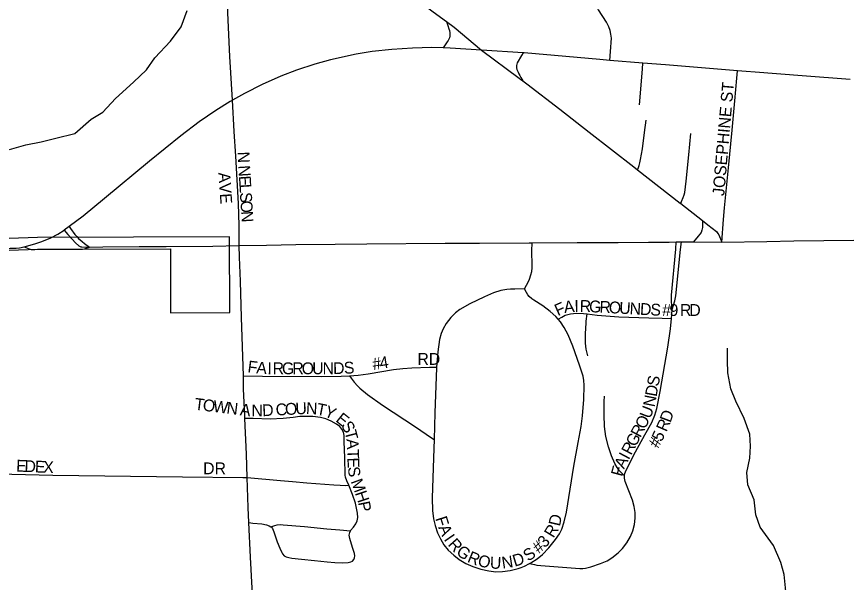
# Model space of a CAD drawing. Extents: x 1442749 to 1756758, y 235267 to 677782.
# Drawn here: x 1585804 to 1589318, y 527823 to 530215 of the extents above; entities that cross this region are included whole.
import ezdxf

# ---------------------------------------------------------------- set-up
doc = ezdxf.new("R2010")
doc.units = 0
for name, color, linetype in [('GM_X_City_Street', 7, 'Continuous'), ('GM_X_City_Street_Text', 7, 'Continuous'), ('GM_X_Corporation', 7, 'Continuous'), ('GM_X_Interchange_Ramps', 7, 'Continuous'), ('GM_X_Minor_River', 7, 'Continuous'), ('GM_X_State_Route', 7, 'Continuous'), ('GM_X_US_Route', 7, 'Continuous')]:
    doc.layers.add(name, color=color, linetype=linetype)

msp = doc.modelspace()

# ---------------------------------------------------------------- linework, layer by layer
at = {"layer": 'GM_X_City_Street'}
for points in [[(1586717, 529861.9), (1586706.7, 530046.1), (1586695.3, 530294.8), (1586687.2, 530448.6), (1586673.8, 530772)], [(1588313.2, 530030.2), (1588316.3, 530068.1), (1588319.9, 530123.8), (1588318.2, 530141.2), (1588315.2, 530155.9), (1588309.4, 530172.5), (1588299.5, 530192.3), (1588265.4, 530244.4), (1588253.4, 530268.3), (1588241.9, 530299.6), (1588241.1, 530303)], [(1588438.4, 529841.4), (1588443.2, 529890.8), (1588451.7, 529994.9), (1588453.6, 530018.8)], [(1588787.1, 529262), (1588794.1, 529357.4), (1588797.9, 529406.1), (1588814.7, 529575.5), (1588830.2, 529734.9), (1588841.5, 529858.7), (1588850.5, 529955), (1588853.3, 529985.8)], [(1586745.7, 529246.9), (1586745.4, 529331.6), (1586742.4, 529425.2), (1586731.6, 529624.4), (1586724.5, 529728.9), (1586717, 529861.9)], [(1588431, 529567.2), (1588435.1, 529577.1), (1588437.9, 529585.1), (1588440.7, 529596.1), (1588443, 529610.8), (1588450.9, 529656.3), (1588459.8, 529724.9), (1588467.2, 529777.1)], [(1588613.4, 529425.2), (1588616.7, 529433.1), (1588623.6, 529449.6), (1588627.7, 529461.3), (1588630, 529471.7), (1588636.8, 529519.5), (1588647.7, 529630), (1588655.7, 529721.1)], [(1586763.6, 528695.9), (1586754.8, 528942.3), (1586750.9, 529096.4), (1586747.4, 529198), (1586745.7, 529246.9)], [(1588094.8, 528936), (1588085.3, 528946.9), (1588061.6, 528968.7), (1588030.4, 528991.9), (1587991.5, 529016.6), (1587983.5, 529022.1), (1587971.9, 529031.9), (1587966, 529039.3), (1587960.9, 529048.1), (1587953.1, 529064.3), (1587969.7, 529095.7), (1587974.2, 529105.2), (1587979.4, 529122.6), (1587982.9, 529137.6), (1587984.6, 529152.6), (1587985.2, 529175.6), (1587983.9, 529211.8), (1587984.1, 529224.9), (1587984.5, 529258.6)], [(1588577, 528976.3), (1588573.8, 529010.9), (1588574.3, 529036.7), (1588591.9, 529232.2), (1588594.6, 529262.2)], [(1588577, 528976.3), (1588589, 529012.7), (1588592.9, 529034.8), (1588612.9, 529230), (1588616.2, 529262.3)], [(1587953.1, 529064.3), (1587911.9, 529062.9), (1587893.5, 529062.5), (1587877.6, 529061.3), (1587852.6, 529056.8), (1587821.8, 529047.2), (1587782.7, 529030.8), (1587720.9, 529000.9), (1587678.7, 528976.8), (1587661.1, 528963.1), (1587641.2, 528942.3), (1587621.3, 528916.9), (1587608.1, 528895), (1587599.7, 528874.5), (1587593.4, 528849.7), (1587585.8, 528798.2), (1587580.8, 528733.4)], [(1588094.8, 528936), (1588110.2, 528944.2), (1588124.9, 528952), (1588135.1, 528955.7), (1588147.1, 528958.5), (1588172.3, 528961.3), (1588201.5, 528959.7), (1588217.7, 528957.6)], [(1588220.4, 528780.3), (1588212.9, 528808.9), (1588209.8, 528834.9), (1588209.8, 528874.3), (1588213.2, 528920.1), (1588213.9, 528926.6), (1588217.7, 528957.6)], [(1588217.7, 528957.6), (1588259.9, 528952.1), (1588351.3, 528946), (1588478.7, 528942), (1588534.3, 528940.3), (1588574.2, 528939.1)], [(1588574.2, 528939.1), (1588575.7, 528955.1), (1588577, 528976.3)], [(1587973.5, 527902.3), (1587978.9, 527905), (1588005.9, 527922.6), (1588028.2, 527941.1), (1588055.3, 527968.9), (1588084.1, 528004.1), (1588100, 528028.3), (1588109.8, 528048.4), (1588120.4, 528078.7), (1588130.1, 528119.8), (1588161.3, 528314.1), (1588179.9, 528414.2), (1588192.6, 528481.7), (1588198.1, 528527), (1588201.9, 528579.2), (1588203.8, 528595.3), (1588205.4, 528657.1), (1588204, 528676.2), (1588200.5, 528694.9), (1588185.6, 528741.3), (1588156.6, 528821.3), (1588137.1, 528869.7), (1588120.7, 528901.2), (1588104.3, 528925.1), (1588094.8, 528936)], [(1588375.7, 528273.5), (1588375.9, 528276), (1588377.3, 528283.6), (1588380, 528290.9), (1588396.4, 528326), (1588422.5, 528375.1), (1588462, 528446.8), (1588490.7, 528498.7), (1588503.8, 528529.4), (1588512.2, 528558.1), (1588526.3, 528629.2), (1588558.9, 528816.7), (1588570.1, 528894.9), (1588574.2, 528939.1)], [(1587212.2, 528696.8), (1587249.2, 528699.6), (1587290.6, 528703.9), (1587397.9, 528722.3), (1587437.2, 528726.5), (1587475.9, 528729.6), (1587550.9, 528732.3), (1587580.8, 528733.4)], [(1587580.8, 528733.4), (1587580.5, 528729.8), (1587573.6, 528539.7), (1587569.9, 528426.3)], [(1586763.6, 528695.9), (1586844.7, 528694.8), (1587094.5, 528693.2), (1587177.2, 528694.8), (1587212.2, 528696.8)], [(1586769.3, 528516.1), (1586768.9, 528525.7), (1586764.5, 528640.5), (1586763.6, 528695.9)], [(1587212.2, 528696.8), (1587219.7, 528686.2), (1587231.5, 528669.6), (1587245.6, 528653.6), (1587255.6, 528643.3), (1587288.2, 528616.9), (1587351.9, 528571.5), (1587491.2, 528480), (1587558.9, 528433.8), (1587569.9, 528426.3)], [(1588375.7, 528273.5), (1588368.4, 528280.5), (1588358.3, 528290.2), (1588350.5, 528298.8), (1588343.9, 528308.5), (1588334.1, 528325), (1588319.8, 528358.1), (1588307.6, 528395.6), (1588297.1, 528440.3), (1588291.3, 528482.5), (1588288.8, 528531.7), (1588289.8, 528587.5), (1588290.7, 528610.4)], [(1587208.8, 528233.5), (1587201.1, 528252.5), (1587195.7, 528267), (1587193.9, 528276.4), (1587191.9, 528349.5), (1587190.1, 528418.5), (1587189.1, 528443.5), (1587186.4, 528457.3), (1587180.5, 528470.3), (1587171.4, 528481.3), (1587157.6, 528491.8), (1587134.3, 528505.1), (1587112.4, 528514.1), (1587089.5, 528520), (1587057.5, 528523.5), (1587032.8, 528524.5), (1587001.8, 528523.6), (1586973.9, 528520.6), (1586931.8, 528515.8), (1586876.4, 528513.5), (1586804.5, 528515.2), (1586769.3, 528516.1)], [(1586779.2, 528266.7), (1586776, 528365.2), (1586769.3, 528516.1)], [(1587569.9, 528426.3), (1587567.5, 528349.5), (1587562.3, 528179.1), (1587563.7, 528127), (1587567.8, 528091.6), (1587574, 528063.3), (1587584.5, 528032.8), (1587596.7, 528006.6), (1587611.9, 527982), (1587630.2, 527959.6), (1587653.4, 527937.2), (1587676.3, 527919.6), (1587704, 527903.1), (1587733.3, 527889.7), (1587767.1, 527878.5), (1587801.8, 527870.9), (1587830.6, 527868), (1587859.5, 527868.8), (1587891.4, 527873.3), (1587925.8, 527881.9), (1587937.8, 527886.1), (1587953.1, 527892), (1587973.5, 527902.3)], [(1585674.5, 528291.5), (1585682.8, 528286.9), (1585688.3, 528284.8), (1585693.7, 528283.5), (1585699.6, 528282.3), (1585711.7, 528281), (1585724.7, 528281.4), (1585957.7, 528276.4), (1586505.5, 528269.3), (1586761.6, 528266.9), (1586779.2, 528266.7)], [(1586779.2, 528266.7), (1586921, 528253.7), (1586971.9, 528249.3), (1587032.4, 528244.4), (1587146.6, 528235.1), (1587172.2, 528233.5), (1587195.7, 528233), (1587208.8, 528233.5)], [(1586786.5, 528076.5), (1586783.3, 528138.9), (1586779.2, 528266.7)], [(1587973.5, 527902.3), (1587995, 527898.2), (1588005.1, 527896.2), (1588021.5, 527893.8), (1588150.4, 527883.9), (1588186.9, 527881.2), (1588199.4, 527881.4), (1588210.5, 527883), (1588233.5, 527888.2), (1588274.3, 527902), (1588301.8, 527914.2), (1588321.9, 527926.6), (1588348, 527947.4), (1588366.7, 527966.7), (1588385, 527990.5), (1588400.4, 528016.5), (1588411, 528041.2), (1588417.8, 528067.3), (1588421, 528094), (1588420.6, 528117.6), (1588416.4, 528144.2), (1588409.1, 528170), (1588378.1, 528249.3), (1588375.2, 528264.1), (1588375.7, 528273.5)], [(1587216.4, 528040.9), (1587216.9, 528041.8), (1587229.1, 528056.5), (1587239.5, 528070.3), (1587245.3, 528083.4), (1587247.6, 528097.5), (1587246.8, 528114.8), (1587237.8, 528157.2), (1587224.6, 528194.7), (1587208.8, 528233.5)], [(1586786.5, 528076.5), (1586804, 528073.6), (1586842.1, 528069.7), (1586861.6, 528065.8), (1586872.8, 528062.3), (1586879.4, 528058.2)], [(1586876.4, 526785.5), (1586873, 526827.1), (1586863.2, 526974.4), (1586856.3, 527075.7), (1586842.7, 527235.7), (1586830.1, 527402.6), (1586821.7, 527513.6), (1586808.7, 527670.4), (1586801.2, 527798.2), (1586794, 527929.2), (1586786.5, 528076.5)], [(1586879.4, 528058.2), (1586896.2, 528063), (1586906.5, 528065.9), (1586921.1, 528067.6), (1586932.1, 528066.7), (1587022.5, 528058.8), (1587115.8, 528049.8), (1587171.4, 528044.7), (1587216.4, 528040.9)], [(1586879.4, 528058.2), (1586882.7, 528056.2), (1586887.1, 528050.1), (1586891.8, 528036.5), (1586906.5, 527994.6), (1586917.2, 527967.3), (1586925.5, 527948.8), (1586929.2, 527943), (1586936.5, 527935.7), (1586943.8, 527931.3), (1586955.5, 527927.6), (1586968.7, 527925.4), (1587009.7, 527920.3), (1587064.6, 527914.6), (1587117.3, 527909.5), (1587150.5, 527907.5), (1587183.6, 527905.8), (1587206.1, 527906.8), (1587217.7, 527909.3), (1587224.8, 527913.1), (1587230.4, 527919.2), (1587233.7, 527926.5), (1587234.6, 527934.4), (1587233.1, 527945.2), (1587225, 527970.7), (1587213.4, 528007.9), (1587211.5, 528022.9), (1587213.2, 528034.3), (1587216.4, 528040.9)]]:
    msp.add_lwpolyline(points, dxfattribs=at)
at = {"layer": 'GM_X_Corporation'}
msp.add_lwpolyline([(1584541.8, 529206), (1585025.8, 529204.8), (1585132.8, 529204.4), (1585893, 529231.5), (1586454.6, 529233.2), (1586455.5, 528963.2), (1586705.5, 528964), (1586704.8, 529284), (1585893.1, 529281.5), (1585133, 529254.4), (1584541.9, 529256.3)], close=True, dxfattribs=at)
at = {"layer": 'GM_X_Interchange_Ramps'}
for points in [[(1587622, 530194.3), (1587627.9, 530178), (1587632.6, 530164), (1587634.9, 530155.8), (1587636.9, 530146.1), (1587637.2, 530138.4), (1587636.5, 530132), (1587634.9, 530125.4), (1587629.2, 530113.5), (1587625.5, 530108), (1587607.8, 530082.4)], [(1587947.2, 530061.9), (1587940.5, 530050.7), (1587921.3, 530019.4), (1587919.5, 530013.3), (1587918.4, 530008.3), (1587918.7, 529998.5), (1587920.2, 529991.4), (1587922.6, 529986), (1587925.7, 529979.6), (1587929.1, 529973.4), (1587932.6, 529966.5), (1587937.2, 529957.9), (1587945, 529943.2)], [(1588705.4, 529352.4), (1588705.8, 529336.9), (1588704.8, 529323.1), (1588702.9, 529311.6), (1588699.2, 529302.2), (1588694.1, 529294.9), (1588687, 529286.4), (1588666.9, 529262.6)], [(1585836.9, 529241.5), (1585850.2, 529235.5), (1585857.5, 529232.8), (1585866.2, 529230.9), (1585880.7, 529230.3), (1585952.3, 529232.1), (1586069.1, 529231.6), (1586083.2, 529232), (1586092, 529233.5), (1586098.1, 529235.3), (1586112.5, 529240.5)]]:
    msp.add_lwpolyline(points, dxfattribs=at)
at = {"layer": 'GM_X_Minor_River'}
for points in [[(1585774.8, 529653.1), (1585843.2, 529672.4), (1585907.5, 529685.7), (1585969.8, 529701), (1586050.2, 529720.2), (1586119.1, 529781.5), (1586169.5, 529811), (1586222.3, 529868.6), (1586299.3, 529937.9), (1586354, 529989.5), (1586388.7, 530041.2), (1586455.7, 530110.7), (1586500.5, 530172.3), (1586525.4, 530240.3)], [(1589123.9, 527496.9), (1589097.4, 527556.7), (1589077.9, 527609.1), (1589066.7, 527677.4), (1589061.4, 527739.7), (1589056.1, 527799.9), (1589050.8, 527856.1), (1589037.3, 527906.4), (1589006.1, 527979), (1588948.9, 528055.9), (1588931.5, 528108.3), (1588924.2, 528172.5), (1588896.9, 528235.1), (1588893.5, 528287.3), (1588906.2, 528347.3), (1588908.8, 528399.4), (1588905.4, 528449.6), (1588882.1, 528516.1), (1588846.9, 528588.7), (1588825.5, 528641.1), (1588812.3, 528709.5), (1588810.9, 528761.6), (1588811.5, 528813.8)]]:
    msp.add_lwpolyline(points, dxfattribs=at)
at = {"layer": 'GM_X_State_Route'}
for points in [[(1586746.4, 530857.2), (1586877.3, 530757), (1587023.5, 530646), (1587063.9, 530615.3), (1587232.5, 530487.3), (1587465.4, 530311.5), (1587566.5, 530235.8), (1587622, 530194.3), (1587654.4, 530170), (1587770.1, 530073.9)], [(1587770.1, 530073.9), (1587929.5, 529954.4), (1587932.1, 529952.5)], [(1587932.1, 529952.5), (1587945, 529943.2), (1587962.5, 529930.5), (1588101.5, 529823.3), (1588225.6, 529726.3), (1588414.8, 529579.6), (1588431, 529567.2), (1588611.6, 529426.6), (1588613.4, 529425.2), (1588705.4, 529352.4), (1588727.4, 529335), (1588763.9, 529306.2), (1588770.8, 529298.4), (1588774.6, 529292.2), (1588787.1, 529262)]]:
    msp.add_lwpolyline(points, dxfattribs=at)
at = {"layer": 'GM_X_US_Route'}
for points in [[(1587770.1, 530073.9), (1587637.8, 530081.1), (1587607.8, 530082.4), (1587559.9, 530084.4), (1587478.2, 530081.9), (1587390.8, 530076.3), (1587308.7, 530067.1), (1587241, 530055.9), (1587132.3, 530032.2), (1587066.1, 530013.9), (1586988.5, 529988.5), (1586921.3, 529962.9), (1586843.6, 529928.1), (1586767.5, 529890.1), (1586717, 529861.9), (1586707.6, 529856.7), (1586646.7, 529818.5), (1586576.7, 529770.1), (1586498.3, 529710.9), (1586365.7, 529603.8), (1586176.4, 529446.6), (1586085.5, 529371.1), (1586026.2, 529326.9), (1586006.1, 529311.9)], [(1588890, 529982.8), (1588853.3, 529985.8), (1588548.6, 530011), (1588453.6, 530018.8), (1588313.2, 530030.2), (1588270.7, 530033.9), (1588126.9, 530046.2), (1587950.5, 530061.6), (1587947.2, 530061.9), (1587770.1, 530073.9)], [(1589330.1, 529949.3), (1589127.4, 529965), (1588927.8, 529979.6), (1588890, 529982.8)], [(1585093.1, 529228.7), (1585159, 529229.5), (1585332.5, 529230.2), (1585538.9, 529233.5), (1585663.1, 529234.4), (1585776.8, 529235.3), (1585788.8, 529235.4), (1585802.8, 529236.1), (1585816.2, 529237.5), (1585836.9, 529241.5), (1585880.9, 529254.8), (1585910.9, 529264.8), (1585948.9, 529279.5), (1585978.4, 529294.8), (1586006.1, 529311.9)], [(1586006.1, 529311.9), (1586021, 529294.2), (1586038.6, 529274.5), (1586053.9, 529258.7), (1586067.7, 529246.2), (1586070.4, 529244.4), (1586075.6, 529242.1), (1586080.1, 529241.5), (1586112.5, 529240.5)], [(1586026.2, 529326.9), (1586031.6, 529319.5), (1586050.7, 529294), (1586058.5, 529285.6), (1586066.3, 529277.4), (1586081.8, 529264.2), (1586092, 529256.4), (1586112.5, 529240.5)], [(1588787.1, 529262), (1588976.9, 529264.8), (1589091.7, 529266.9), (1589345.6, 529269.7)], [(1586112.5, 529240.5), (1586168.4, 529241.2), (1586322.4, 529242.5), (1586437.2, 529243.7), (1586633.9, 529245), (1586745.7, 529246.9), (1586861.7, 529248.9)], [(1586861.7, 529248.9), (1586984.7, 529251), (1587151.9, 529253), (1587286.3, 529254.7), (1587617.5, 529257.2), (1587752.5, 529256.6)], [(1587752.5, 529256.6), (1587761.9, 529256.6), (1587972.7, 529258.5), (1587984.5, 529258.6), (1588174.8, 529260.1), (1588348.6, 529260), (1588476.5, 529261.4), (1588565, 529262), (1588594.6, 529262.2), (1588616.2, 529262.3), (1588666.9, 529262.6), (1588787.1, 529262)]]:
    msp.add_lwpolyline(points, dxfattribs=at)

# ---------------------------------------------------------------- texts
at = {"layer": 'GM_X_City_Street_Text'}
for s, rotation, p in [('JOSEPHINE ST', 85.031, (1588797, 529455.3)), ('N', 272.295, (1586739, 529643.4)), ('AVE', 273.9506, (1586657.5, 529555.1)), ('N', 273.5684, (1586741.6, 529585)), ('E', 273.5525, (1586744.3, 529541.1)), ('L', 273.6051, (1586746.5, 529505.9)), ('S', 273.5797, (1586748.7, 529470.8)), ('O', 273.5684, (1586750.9, 529435.6)), ('N', 273.5807, (1586753.6, 529391.7)), ('F', 23.8515, (1588093.2, 528948.1)), ('A', 6.7022, (1588121.6, 528961.3)), ('I', 1.3119, (1588164, 528966.4)), ('R', 358.3482, (1588185.4, 528966.9)), ('G', 357.1572, (1588224.7, 528965.7)), ('R', 356.9387, (1588268.5, 528963.6)), ('O', 356.9866, (1588308.1, 528961.5)), ('U', 356.939, (1588352.1, 528959.1)), ('N', 356.9866, (1588396.1, 528956.8)), ('D', 356.939, (1588440, 528954.5)), ('S', 357.112, (1588484.1, 528952.1)), ('#', 359.3713, (1588534.6, 528949.8)), ('9', 359.9305, (1588565.9, 528949.4)), ('R', 359.9941, (1588610, 528949.4)), ('D', 359.9929, (1588649.6, 528949.4)), ('#', 9.0927, (1587313.3, 528720.5)), ('4', 9.1086, (1587343.7, 528725.3)), ('RD', 0, (1587499.6, 528742.6)), ('F', 352.6039, (1586779.3, 528711.7)), ('A', 355.2632, (1586816.7, 528706.9)), ('I', 359.8015, (1586864.9, 528703.1)), ('R', 359.9587, (1586887, 528703)), ('G', 0.0379, (1586926.7, 528703)), ('R', 0, (1586970.7, 528703)), ('O', 0.0379, (1587010.3, 528703)), ('U', 0, (1587054.3, 528703.1)), ('N', 0.0379, (1587098.3, 528703.1)), ('D', 1.2095, (1587143.4, 528703.1)), ('S', 3.9805, (1587190.1, 528704.2)), ('S', 79.5746, (1588518.9, 528649)), ('D', 79.5699, (1588510.9, 528605.7)), ('T', 353.0444, (1586554.7, 528553.3)), ('N', 78.9426, (1588502.4, 528561.9)), ('O', 353.0613, (1586589.7, 528549.1)), ('W', 353.0564, (1586633.4, 528543.8)), ('N', 353.0613, (1586690.1, 528536.8)), ('A', 353.4568, (1586747.3, 528529.9)), ('N', 0.432, (1586797.7, 528524.5)), ('D', 3.0954, (1586844.2, 528525)), ('C', 3.0692, (1586901.3, 528528)), ('O', 3.1057, (1586940.9, 528530.2)), ('U', 3.1047, (1586984.8, 528532.5)), ('N', 356.8953, (1587027.3, 528534.9)), ('T', 348.9473, (1587069.5, 528532.8)), ('Y', 337.1027, (1587101.4, 528526.8)), ('U', 69.0723, (1588484, 528511.8)), ('E', 321.4085, (1587150.6, 528505.7)), ('D', 69.8198, (1588569.6, 528495.5)), ('S', 299.5721, (1587174.9, 528487.5)), ('O', 62.5887, (1588461.3, 528467.1)), ('R', 66.7065, (1588552.9, 528456.3)), ('T', 284.6059, (1587191, 528460.1)), ('R', 62.113, (1588442.5, 528431.7)), ('5', 63.7655, (1588532.3, 528414.3)), ('A', 273.2138, (1587199.4, 528428.6)), ('G', 62.0853, (1588421.9, 528392.8)), ('#', 63.4908, (1588518.5, 528386.5)), ('R', 62.0761, (1588403.4, 528357.8)), ('T', 272.1039, (1587201.9, 528384.9)), ('I', 62.0664, (1588393.1, 528338.3)), ('E', 357.4341, (1585801.5, 528291.6)), ('D', 357.4203, (1585836.7, 528290)), ('E', 357.4341, (1585880.7, 528288)), ('X', 357.6131, (1585916, 528286.4)), ('DR', 0, (1586593.2, 528279.9)), ('E', 272.0766, (1587203.2, 528349.7)), ('A', 63.3763, (1588373.5, 528299.3)), ('S', 276.9976, (1587204.8, 528309.9)), ('F', 74.97, (1588365.3, 528267.7)), ('M', 290.0998, (1587216.9, 528250.1)), ('H', 288.2276, (1587234.9, 528200.9)), ('P', 281.3314, (1587248.2, 528160.7)), ('D', 77.0525, (1588101.9, 528057.6)), ('F', 287.5105, (1587574.6, 528093.4)), ('A', 292.9599, (1587587, 528055)), ('R', 58.8588, (1588074.9, 528007.6)), ('I', 304.8729, (1587609.6, 528004.6)), ('R', 311.3224, (1587626, 527981.7)), ('3', 47.3681, (1588039, 527966.1)), ('G', 322.5843, (1587660, 527944.6)), ('S', 35.4582, (1587968.7, 527909.3)), ('#', 42.8857, (1588013.4, 527942.1)), ('R', 337.7479, (1587707.4, 527910.7)), ('O', 346.2928, (1587751.8, 527893.2)), ('N', 8.8334, (1587859.9, 527880.3)), ('D', 16.9246, (1587910.8, 527888.7)), ('U', 357.9549, (1587805.5, 527881.2))]:
    msp.add_text(s, height=50, rotation=rotation, dxfattribs=at).set_placement(p)

doc.saveas('drawing.dxf')
